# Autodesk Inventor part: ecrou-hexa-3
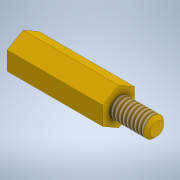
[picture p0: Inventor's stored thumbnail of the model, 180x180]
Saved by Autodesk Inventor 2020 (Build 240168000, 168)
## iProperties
Created: 2021-10
Part Number: ecrou-hexa-3
Material: Générique
Document SubType Name: Modeling
Designer: bruno
Density: 1 g/cm^3
Appearance: Or
Author: bruno
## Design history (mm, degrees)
sketch "Esquisse1"
  geometry: L1 (-2.887, 0)-(-1.443, 2.5); L2 (-1.443, 2.5)-(1.443, 2.5); L3 (1.443, 2.5)-(2.887, 0); L4 (2.887, 0)-(1.443, -2.5); L5 (1.443, -2.5)-(-1.443, -2.5); L6 (-1.443, -2.5)-(-2.887, 0); C1 r 1.5 at (0, 0); 2 further points
  constraints: 12 end point, 2 coincident, 1 centre point, 13 other
  dimensions: "d0" = 5 distance between parallel lines of L2 L5; "d1" = 3 diameter of C1
extrude "Extrusion1" new body sketch "Esquisse1" distance "d2" = 15; taper "d3" = 0 deg
feature "Filetage1" dims "d4" = 17, "d5" = 0
sketch "Esquisse2"
  geometry: C1 r 1.541 at (0, 0); 1 further point
  constraints: 1 centre point, 1 coincident
extrude "Extrusion2" join sketch "Esquisse2" distance "d6" = 6; taper "d7" = 0 deg
chamfer "Chanfrein1" distance "d8" = 0.5; stored, may be unused: second distance "d9" = 2, angle "d10" = 45 deg
feature "Filetage2" dims "d11" = 5.5, "d12" = 0
node "Solide1"
